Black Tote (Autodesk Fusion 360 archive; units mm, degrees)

design "Black Tote" references "assorted terminals 1", "igubal spherical rod end bearing", "2in Hex Hub Half", "40A Circuit Breaker", "iglide plastic thrust washer", "Sushi Roller", "2in Compliant Wheel", "Color Sensor", "circuit breaker", "Spark Max Mounting Bracket", "CIM Motor", "20A Circuit Breaker", "e-chain cable carrier", "Spark Max Motor Controller", "igubal spherical flange bearing", "30A Circuit Breaker", "igubal plastic flange bearing", "Iglide clip bearing", "Robot Signal Light", "igubal plastic sleeve bearing", "assorted terminals 2", "Assorted terminals 3"
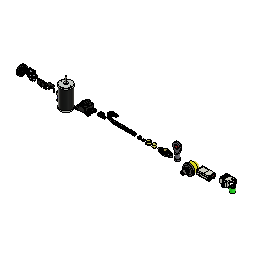
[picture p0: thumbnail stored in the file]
component_insert "Component Insert1"
component_insert "Component Insert2"
component_insert "Component Insert3"
component_insert "Component Insert4"
component_insert "Component Insert5"
component_insert "Component Insert6"
component_insert "Component Insert7"
component_insert "Component Insert8"
component_insert "Component Insert9"
component_insert "Component Insert10"
component_insert "Component Insert11"
component_insert "Component Insert12"
component_insert "Component Insert13"
component_insert "Component Insert14"
component_insert "Component Insert15"
component_insert "Component Insert16"
component_insert "Component Insert17"
component_insert "Component Insert18"
component_insert "Component Insert19"
component_insert "Component Insert20"
component_insert "Component Insert21"
component_insert "Component Insert22"

design "CIM Motor"
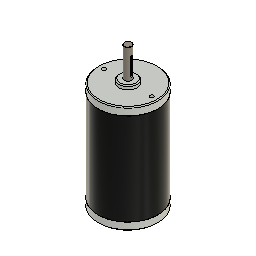
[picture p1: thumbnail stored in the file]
base_feature "Base Feature"
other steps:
create_component "CreateComponent1"

design "Sushi Roller"
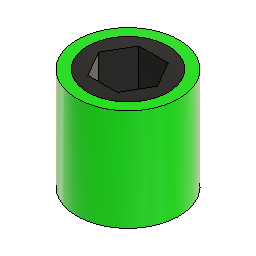
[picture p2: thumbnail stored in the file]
base_feature "Base Feature"

design "Spark Max Mounting Bracket"
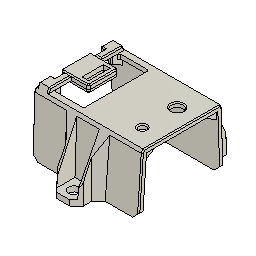
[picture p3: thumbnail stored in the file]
base_feature "Base Feature"
joint "Assemble1" alignAngle 0 alignOffsetX 0 alignOffsetY 0 alignOffsetZ 0
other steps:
create_component "CreateComponent1"
joint_origin "JointOrigin1"
joint_origin "JointOrigin1"

design "Color Sensor"
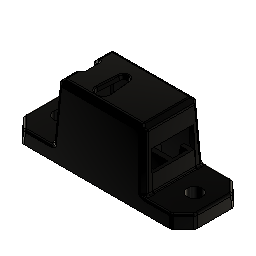
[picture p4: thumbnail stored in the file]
base_feature "Base Feature1"
base_feature "Base Feature1"
base_feature "Base Feature1"
base_feature "Base Feature1"
as_built_joint "As-built1"
joint "Assemble1" alignAngle 0 alignOffsetX 0 alignOffsetY 0 alignOffsetZ 0
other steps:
create_component "CreateComponent1"
create_component "CreateComponent2"
create_component "CreateComponent3"
create_component "CreateComponent4"
joint_origin "JointOrigin1"
joint_origin "JointOrigin1"

design "Robot Signal Light"
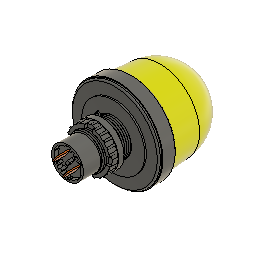
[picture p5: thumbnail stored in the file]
base_feature "Base Feature"

design "Spark Max Motor Controller"
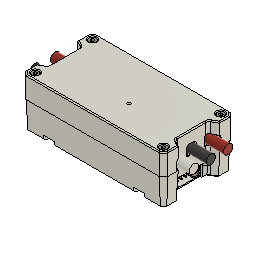
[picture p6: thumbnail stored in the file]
base_feature "Base Feature1"
base_feature "Base Feature1"
base_feature "Base Feature1"
base_feature "Base Feature1"
base_feature "Base Feature1"
base_feature "Base Feature1"
base_feature "Base Feature1"
base_feature "Base Feature1"
base_feature "Base Feature1"
base_feature "Base Feature1"
base_feature "Base Feature1"
base_feature "Base Feature1"
base_feature "Base Feature1"
base_feature "Base Feature1"
base_feature "Base Feature1"
base_feature "Base Feature1"
base_feature "Base Feature1"
base_feature "Base Feature1"
as_built_joint "As-built1"
joint "Assemble1" alignAngle 0 alignOffsetX 0 alignOffsetY 0 alignOffsetZ 0
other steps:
create_component "CreateComponent1"
create_component "CreateComponent2"
create_component "CreateComponent3"
create_component "CreateComponent4"
create_component "CreateComponent5"
create_component "CreateComponent6"
create_component "CreateComponent7"
create_component "CreateComponent8"
create_component "CreateComponent9"
create_component "CreateComponent10"
create_component "CreateComponent11"
create_component "CreateComponent12"
create_component "CreateComponent13"
create_component "CreateComponent14"
create_component "CreateComponent15"
create_component "CreateComponent16"
create_component "CreateComponent17"
create_component "CreateComponent18"
joint_origin "JointOrigin1"
joint_origin "JointOrigin1"

design "2in Hex Hub Half"
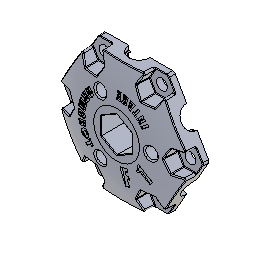
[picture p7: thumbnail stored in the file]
base_feature "Base Feature"

design "40A Circuit Breaker"
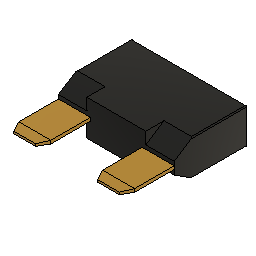
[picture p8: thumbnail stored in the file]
base_feature "Base Feature"

design "iglide plastic thrust washer"
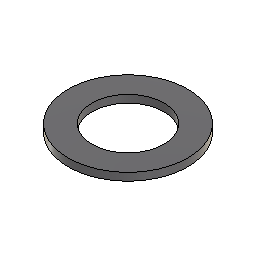
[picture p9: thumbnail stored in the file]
base_feature "Base Feature"

design "igubal plastic sleeve bearing"
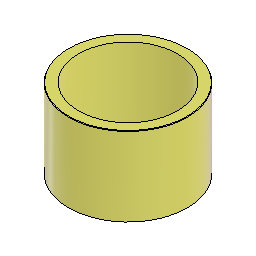
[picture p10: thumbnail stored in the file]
base_feature "Base Feature"

design "igubal plastic flange bearing"
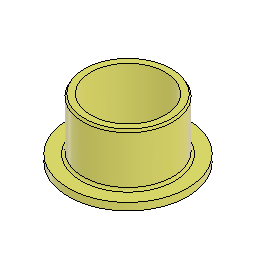
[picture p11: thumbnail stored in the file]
base_feature "Base Feature"

design "circuit breaker"
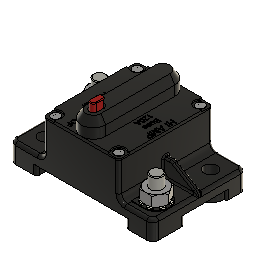
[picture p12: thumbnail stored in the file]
base_feature "Base Feature1"
base_feature "Base Feature1"
base_feature "Base Feature1"
base_feature "Base Feature1"
base_feature "Base Feature1"
base_feature "Base Feature1"
base_feature "Base Feature1"
as_built_joint "As-built1"
joint "Assemble1" alignAngle 0 alignOffsetX 0 alignOffsetY 0 alignOffsetZ 0
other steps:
create_component "CreateComponent1"
create_component "CreateComponent2"
create_component "CreateComponent3"
create_component "CreateComponent4"
create_component "CreateComponent5"
create_component "CreateComponent6"
create_component "CreateComponent7"
joint_origin "JointOrigin1"
joint_origin "JointOrigin1"

design "Iglide clip bearing"
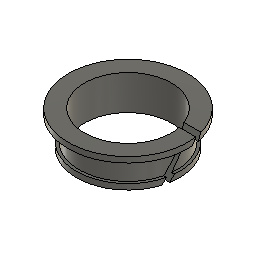
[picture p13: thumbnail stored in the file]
base_feature "Base Feature"

design "Assorted terminals 3"
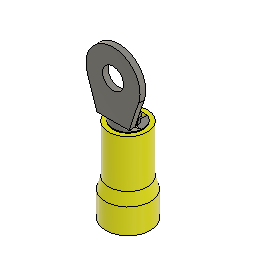
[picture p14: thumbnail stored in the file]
base_feature "Base Feature"

design "e-chain cable carrier"
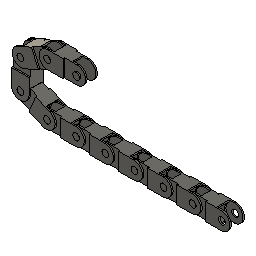
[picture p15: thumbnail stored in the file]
base_feature "Base Feature1"
base_feature "Base Feature1"
base_feature "Base Feature1"
base_feature "Base Feature1"
base_feature "Base Feature1"
base_feature "Base Feature1"
base_feature "Base Feature1"
base_feature "Base Feature1"
base_feature "Base Feature1"
base_feature "Base Feature1"
joint "Assemble1" alignAngle 0 alignOffsetX 0 alignOffsetY 0 alignOffsetZ 0
joint "Assemble2" alignAngle 0 alignOffsetX 0 alignOffsetY 0 alignOffsetZ 0
joint "Assemble3" alignAngle 0 alignOffsetX 0 alignOffsetY 0 alignOffsetZ 0
joint "Assemble4" alignAngle 0 alignOffsetX 0 alignOffsetY 0 alignOffsetZ 0
joint "Assemble5" alignAngle 0 alignOffsetX 0 alignOffsetY 0 alignOffsetZ 0
joint "Assemble6" alignAngle 0 alignOffsetX 0 alignOffsetY 0 alignOffsetZ 0
joint "Assemble7" alignAngle 0 alignOffsetX 0 alignOffsetY 0 alignOffsetZ 0
joint "Assemble8" alignAngle 0 alignOffsetX 0 alignOffsetY 0 alignOffsetZ 0
joint "Assemble9" alignAngle 0 alignOffsetX 0 alignOffsetY 0 alignOffsetZ 0
joint "Assemble10" alignAngle -90 alignOffsetX 0 alignOffsetY 0 alignOffsetZ 0
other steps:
create_component "CreateComponent1"
create_component "CreateComponent2"
create_component "CreateComponent3"
create_component "CreateComponent4"
create_component "CreateComponent5"
create_component "CreateComponent6"
create_component "CreateComponent7"
create_component "CreateComponent8"
create_component "CreateComponent9"
create_component "CreateComponent10"
joint_origin "JointOrigin1"
joint_origin "JointOrigin1"
joint_origin "JointOrigin2"
joint_origin "JointOrigin1"
joint_origin "JointOrigin2"
joint_origin "JointOrigin1"
joint_origin "JointOrigin2"
joint_origin "JointOrigin1"
joint_origin "JointOrigin2"
joint_origin "JointOrigin1"
joint_origin "JointOrigin2"
joint_origin "JointOrigin1"
joint_origin "JointOrigin2"
joint_origin "JointOrigin1"
joint_origin "JointOrigin2"
joint_origin "JointOrigin1"
joint_origin "JointOrigin2"
joint_origin "JointOrigin1"
joint_origin "JointOrigin2"
joint_origin "JointOrigin1"

design "20A Circuit Breaker"
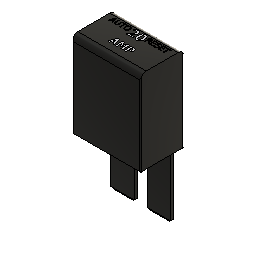
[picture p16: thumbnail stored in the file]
base_feature "Base Feature"

design "assorted terminals 2"
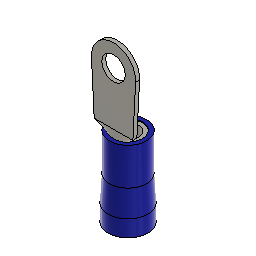
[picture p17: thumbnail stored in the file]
base_feature "Base Feature"

design "2in Compliant Wheel"
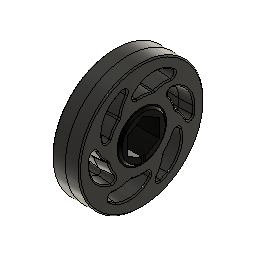
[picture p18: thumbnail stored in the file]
base_feature "Base Feature"

design "igubal spherical rod end bearing"
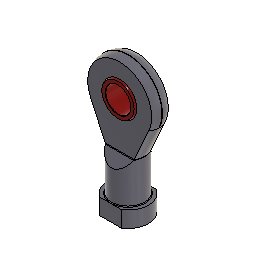
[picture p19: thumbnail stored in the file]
base_feature "Base Feature1"
base_feature "Base Feature1"
joint "Assemble2" alignAngle 0 alignOffsetX 0 alignOffsetY 0 alignOffsetZ 0
joint "Assemble3" alignAngle 0 alignOffsetX 0 alignOffsetY 0 alignOffsetZ 0
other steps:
create_component "CreateComponent1"
create_component "CreateComponent2"
joint_origin "JointOrigin2"
joint_origin "JointOrigin2"
joint_origin "JointOrigin1"
joint_origin "JointOrigin3"

design "igubal spherical flange bearing"
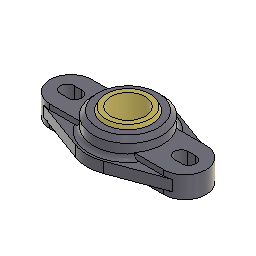
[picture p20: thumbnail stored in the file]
base_feature "Base Feature1"
base_feature "Base Feature1"
joint "Assemble2" alignAngle 90 alignOffsetX 0 alignOffsetY 0 alignOffsetZ 0
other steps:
create_component "CreateComponent1"
create_component "CreateComponent2"
joint_origin "JointOrigin2"
joint_origin "JointOrigin1"

design "30A Circuit Breaker"
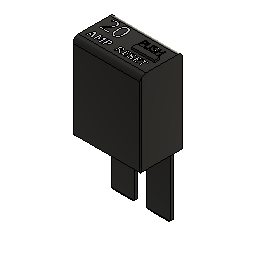
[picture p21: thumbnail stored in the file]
base_feature "Base Feature"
